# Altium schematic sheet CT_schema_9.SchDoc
size 308 x 210 mm
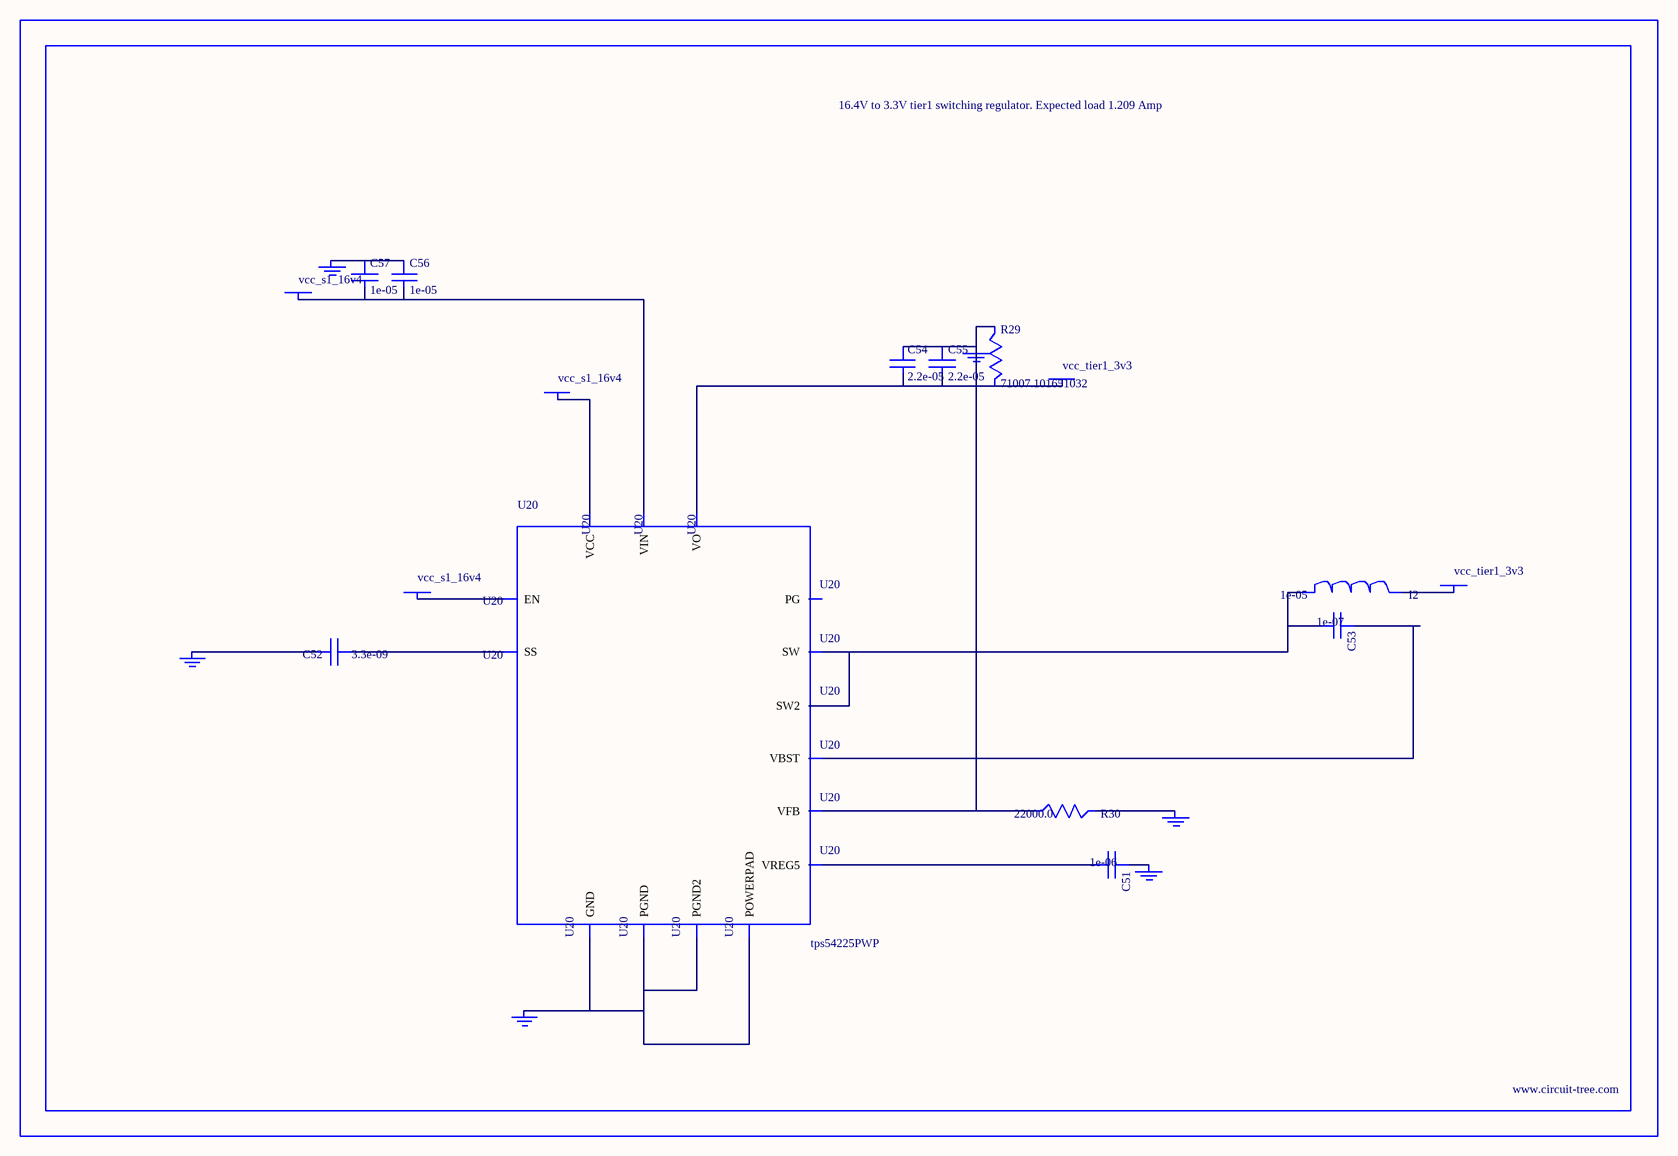
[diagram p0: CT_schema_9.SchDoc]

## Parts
BORDER8  (no value)
C51  1e-06  [C0603]
C52  3.3e-09  [C0402]
C53  1e-07  [C0402]
C54  2.2e-05  [C1210]
C55  2.2e-05  [C1210]
C56  1e-05  [C1206]
C57  1e-05  [C1206]
GND_INSTANCE_8_0  (no value)
GND_INSTANCE_8_1  (no value)
GND_INSTANCE_8_2  (no value)
GND_INSTANCE_8_3  (no value)
GND_INSTANCE_8_4  (no value)
GND_INSTANCE_8_5  (no value)
I2  1e-05  [IND_PM3316]
POWER_INSTANCE_8_0  vcc_tier1_3v3
POWER_INSTANCE_8_1  vcc_s1_16v4
POWER_INSTANCE_8_2  vcc_tier1_3v3
POWER_INSTANCE_8_3  vcc_s1_16v4
POWER_INSTANCE_8_4  vcc_s1_16v4
R29  71007.101651032  [R0603]
R30  22000.0  [R0603]
U20  tps54225PWP  [HTSSOP14]

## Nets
NetC51_1: C51.1 GND_INSTANCE_8_2.0(GND)
NetC51_2: C51.2 U20.3(VREG5)
NetC52_1: C52.1 U20.4(SS)
NetC52_2: C52.2 GND_INSTANCE_8_3.0(GND)
NetC53_1: C53.1 U20.12(VBST)
NetC53_2: C53.2 I2.1 U20.10(SW) U20.11(SW2)
NetC54_1: C54.1 C55.1 GND_INSTANCE_8_0.0(GND) R29.1 R30.1 U20.2(VFB)
NetC54_2: C54.2 C55.2 POWER_INSTANCE_8_0.0(PWR) R29.2 U20.1(VO)
NetC56_1: C56.1 C57.1 GND_INSTANCE_8_5.0(GND)
NetC56_2: C56.2 C57.2 POWER_INSTANCE_8_3.0(PWR) U20.13(VIN)
NetGND_INSTANCE_8_1_0: GND_INSTANCE_8_1.0(GND) R30.2
NetGND_INSTANCE_8_4_0: GND_INSTANCE_8_4.0(GND) U20.5(GND) U20.8(PGND) U20.9(PGND2) U20.15(POWERPAD)
NetI2_2: I2.2 POWER_INSTANCE_8_2.0(PWR)
NetPOWER_INSTANCE_8_1_0: POWER_INSTANCE_8_1.0(PWR) U20.7(EN)
NetPOWER_INSTANCE_8_4_0: POWER_INSTANCE_8_4.0(PWR) U20.14(VCC)

Not connected (* = marked no-connect by the designer): U20 6(PG)

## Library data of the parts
BORDER8 = BORDER_PAGE8
C51 = C0603C105K3RACTU
C52 = C0402C332K3RAC
C53 = C0402C104K3RACTU
C54 C55 = GRM32ER61E226ME15L
C56 C57 = C1206C106K3RACTU
GND_INSTANCE_8_0-GND_INSTANCE_8_5 = GND
I2 = PM3316-100M-RC
POWER_INSTANCE_8_0-POWER_INSTANCE_8_4 = PWR
R29 = R29
R30 = RC0603JR-0722KL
